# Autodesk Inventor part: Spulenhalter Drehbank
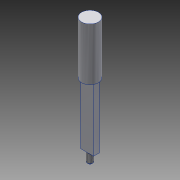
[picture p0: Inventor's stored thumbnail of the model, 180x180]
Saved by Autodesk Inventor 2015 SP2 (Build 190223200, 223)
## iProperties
Created: 2015-10
Part Number: Spulenhalter Drehbank
Material: Aluminium 6061
Document SubType Name: Modeling
Designer: rYan
Mass: 37.1404 g
Surface Area: 49.0848 cm^2
Volume: 13.7557 cm^3
Density: 2.7 g/cm^3
Appearance: Aluminium - flach
Author: rYan
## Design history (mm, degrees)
sketch "Skizze1"
  geometry: C1 r 8 at (0, 0); 1 further point
  constraints: 1 centre point, 1 coincident
  dimensions: "d0" = 16 diameter of C1
extrude "Extrusion1" new body sketch "Skizze1" distance "d1" = 50; taper "d2" = 0 deg
sketch "Skizze2"
  geometry: L1 (-6.25, 2.75)-(6.25, 2.75); L2 (6.25, 2.75)-(6.25, -2.75); L3 (6.25, -2.75)-(-6.25, -2.75); L4 (-6.25, -2.75)-(-6.25, 2.75); L5 (-6.25, 2.75)-(6.25, -2.75); L6 (6.25, 2.75)-(-6.25, -2.75); 1 further point
  constraints: 12 end point, 2 midpoint, 2 parallel, 1 horizontal, 1 perpendicular
  dimensions: "d3" = 12.5 distance of L2.end L3.end; "d4" = 5.5 distance of L1.end L2.end
extrude "Extrusion2" join sketch "Skizze2" distance "d5" = 60; taper "d6" = 0 deg
sketch "Skizze3"
  geometry: C1 r 2.5 at (0, 0); 1 further point
  constraints: 1 centre point, 1 coincident
  dimensions: "d7" = 5 diameter of C1
extrude "Extrusion3" join sketch "Skizze3" distance "d8" = 10; taper "d9" = 0 deg
feature "Gewinde1" dims "d10" = 10, "d11" = 0
chamfer "Chamfer1" distance "d12" = 1; stored, may be unused: second distance "d13" = 2, angle "d14" = 45 deg
node "Volumenkörper1"
